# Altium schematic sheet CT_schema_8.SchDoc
size 226 x 144 mm
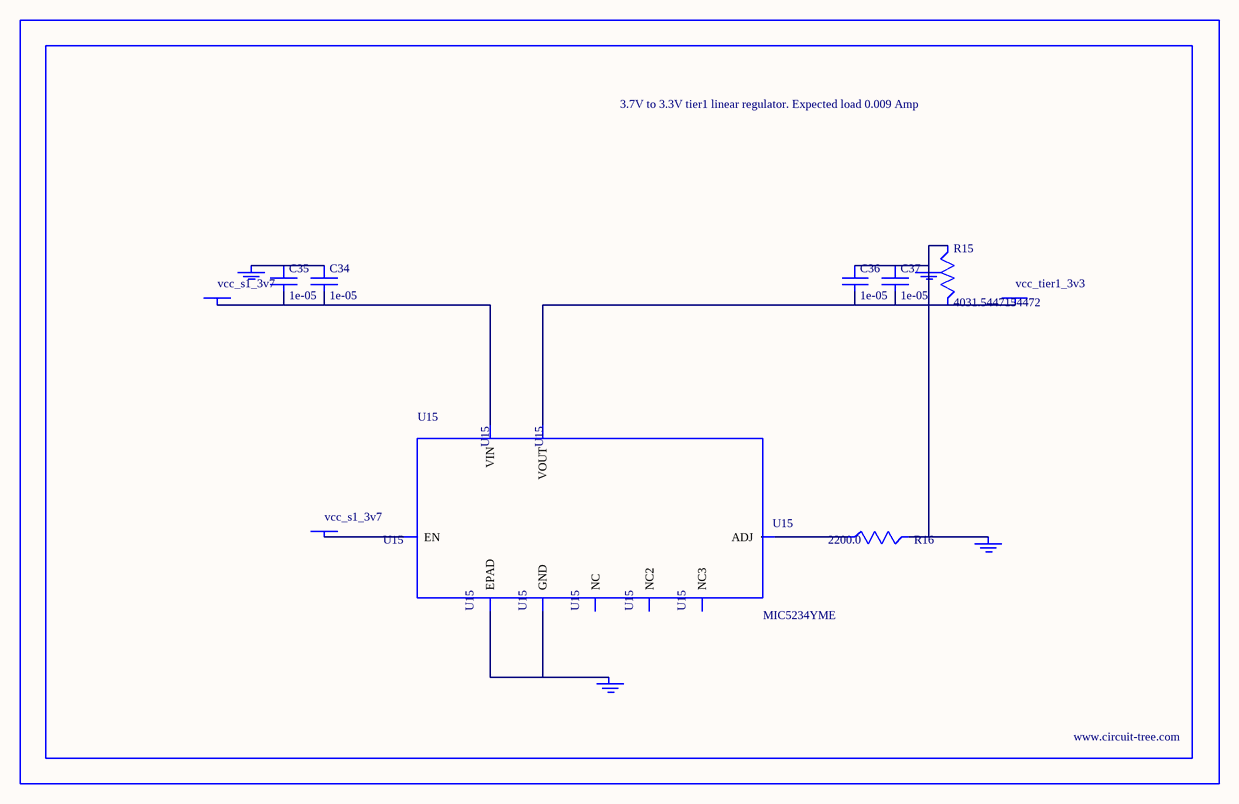
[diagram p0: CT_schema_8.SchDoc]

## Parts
BORDER7  (no value)
C34  1e-05  [C1210]
C35  1e-05  [C1210]
C36  1e-05  [C1210]
C37  1e-05  [C1210]
GND_INSTANCE_7_0  (no value)
GND_INSTANCE_7_1  (no value)
GND_INSTANCE_7_2  (no value)
GND_INSTANCE_7_3  (no value)
POWER_INSTANCE_7_0  vcc_tier1_3v3
POWER_INSTANCE_7_1  vcc_s1_3v7
POWER_INSTANCE_7_2  vcc_s1_3v7
R15  4031.5447154472  [R0603]
R16  2200.0  [R0603]
U15  MIC5234YME  [SOIC-8_EP]

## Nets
NetC34_1: C34.1 C35.1 GND_INSTANCE_7_3.0(GND)
NetC34_2: C34.2 C35.2 POWER_INSTANCE_7_2.0(PWR) U15.8(VIN)
NetC36_1: C36.1 C37.1 GND_INSTANCE_7_0.0(GND) GND_INSTANCE_7_1.0(GND) R15.1 R16.2
NetC36_2: C36.2 C37.2 POWER_INSTANCE_7_0.0(PWR) R15.2 U15.1(VOUT)
NetGND_INSTANCE_7_2_0: GND_INSTANCE_7_2.0(GND) U15.7(GND) U15.EPAD
NetPOWER_INSTANCE_7_1_0: POWER_INSTANCE_7_1.0(PWR) U15.5(EN)
NetR16_1: R16.1 U15.4(ADJ)

Not connected (* = marked no-connect by the designer): U15 2(NC) 3(NC2) 6(NC3)

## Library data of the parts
BORDER7 = BORDER_PAGE7
C34-C37 = C1210C106K5PACTU
GND_INSTANCE_7_0-GND_INSTANCE_7_3 = GND
POWER_INSTANCE_7_0-POWER_INSTANCE_7_2 = PWR
R15 = R15
R16 = RC0603JR-072K2L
